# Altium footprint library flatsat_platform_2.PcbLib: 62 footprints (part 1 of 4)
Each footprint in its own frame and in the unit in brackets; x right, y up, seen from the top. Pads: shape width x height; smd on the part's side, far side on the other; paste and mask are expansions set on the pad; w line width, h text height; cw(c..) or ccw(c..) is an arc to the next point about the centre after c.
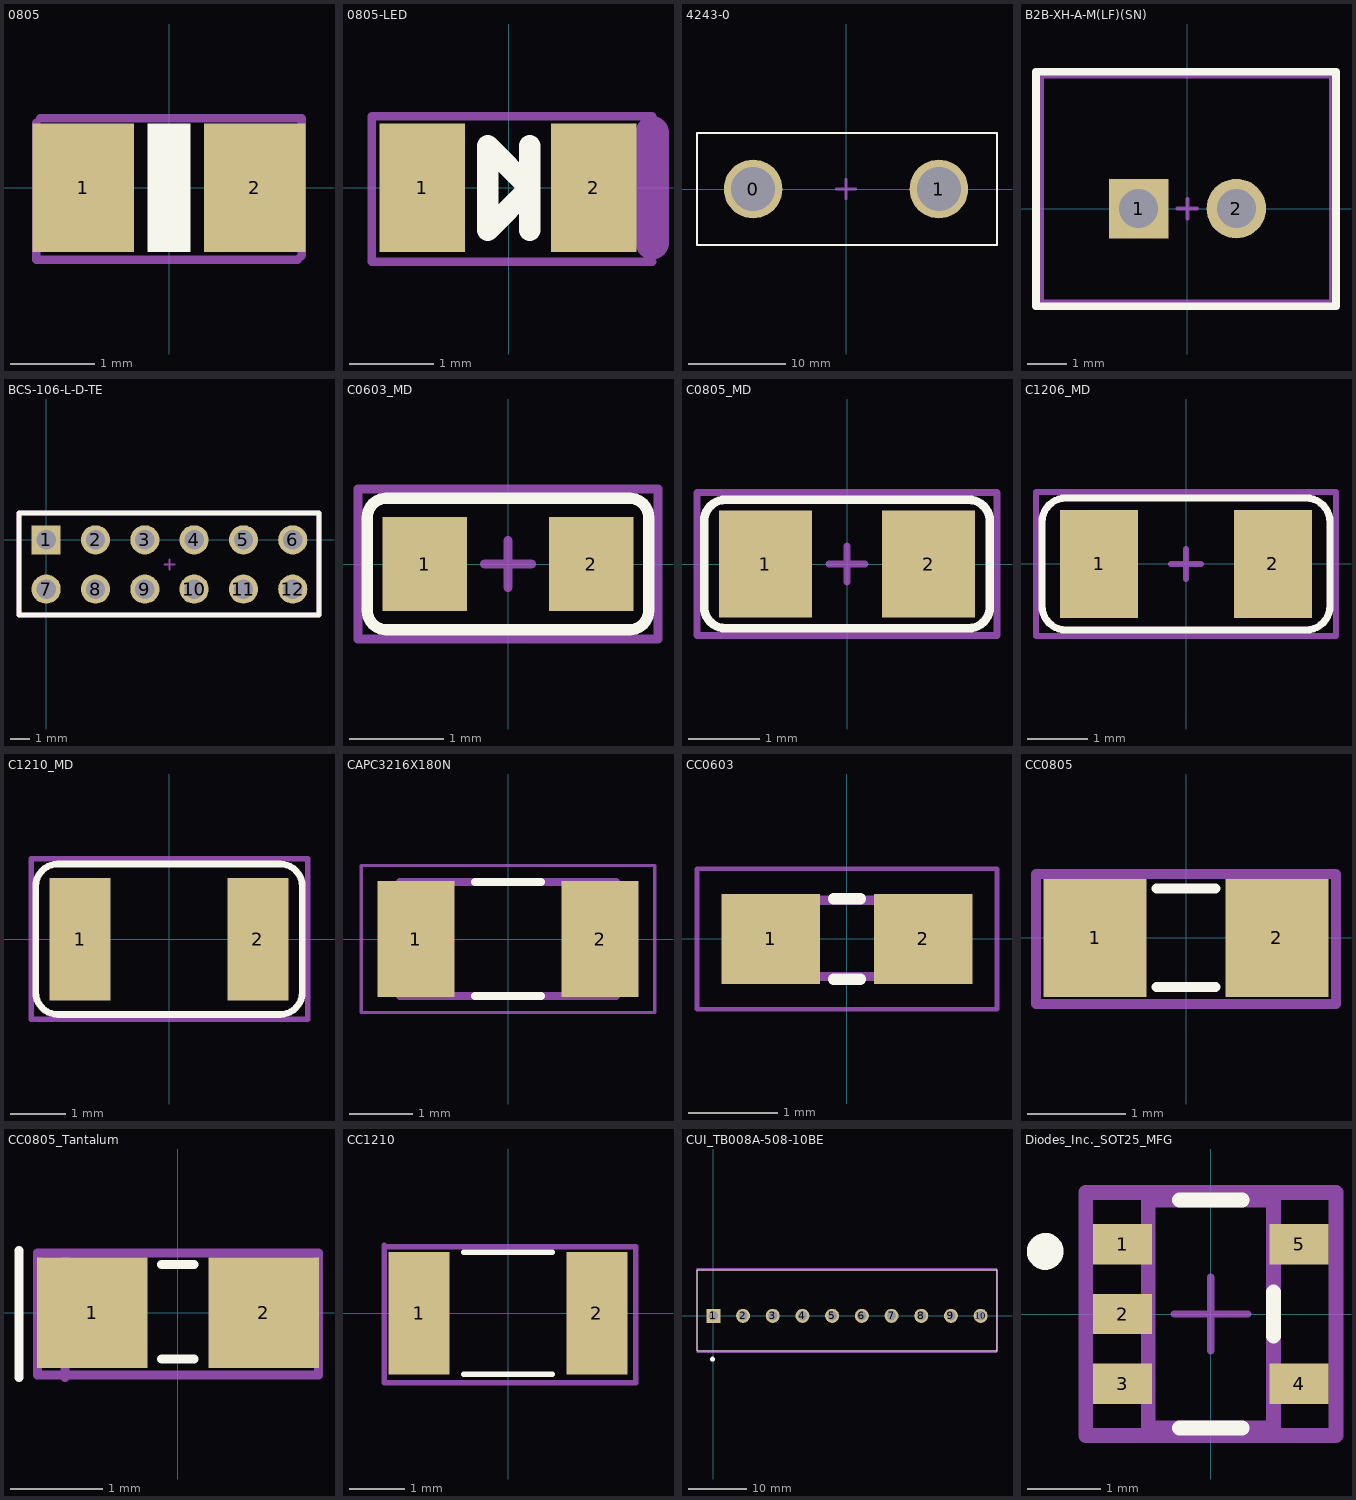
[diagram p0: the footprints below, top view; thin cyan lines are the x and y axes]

## 0805 [mil]
pads (2):
  rect 47.24x60 smd: 1(-40,0) 2(40,0)
Top Overlay:
  rectangle: -10,-30 10,30
Mechanical 15:
  lines w3.94: -62.01,30.51 -62.01,-33.46 60.04,-33.46 62.01,-31.5 62.01,32.48 -60.04,32.48
  text ".Designator" at -58.7,-2.44 h19.68
3D body "RES0805(2012M).STEP": height 31.1, standoff 0, extent -50,-24.49 48.75,24.51

## 0805-LED [mil]
height 122.05
pads (2):
  rect 40x60 smd: 1(-40.35,0) 2(39.65,0)
Top Overlay:
  lines w10: 9.84,-19.68 9.84,19.68 ; -9.84,-19.68 -9.84,19.68 9.84,0 -9.84,-19.68
Mechanical 15:
  lines w3.94: 66.93,-34.45 -63.98,-34.45 -63.98,33.46 66.93,33.46
  lines w15.75: 66.93,-25.59 66.93,25.59
  text ".Designator" at -41.34,-1.97 h19.68
3D body "User Library-led_0805LED0805_red.STEP": height 43.31, standoff 0, extent -39.76,-24.6 39.77,24.61

## 4243-0 [mm]
pads (2):
  round 6 hole 4.5: 0(-9.525,0) 1(9.525,0)
Top Overlay:
  lines w0.2: -15.275,-5.75 -15.275,5.75 15.475,5.75 15.475,-5.75 -15.275,-5.75
Top Assembly:
  lines w0.2: -15.275,-5.75 -15.275,5.75 15.475,5.75 15.475,-5.75 -15.275,-5.75
  lines w0.3: -1,0 1,0 ; 0,-1 0,1
  text "'.Designator'" at -6.525,2.5 h1.2
3D body: height 24.13, standoff 0, extent 3.925,-5.597 15.125,5.597
3D body: height 6, standoff 0, extent -15.125,-5.597 15.275,5.597
3D body: height 24.13, standoff 0, extent -15.125,-5.597 -3.925,5.597

## B2B-XH-A-M(LF)(SN) [mm]
pads (2):
  rect 1.524x1.524 hole 1: 1(-1.25,0)
  round 1.524 hole 1: 2(1.25,0)
Top Overlay:
  lines w0.2: -3.875,-2.5 3.8,-2.5 3.8,3.5 -3.875,3.5 -3.875,0.5 -3.875,-2.5
Top Assembly:
  lines w0.1: -0.25,0 0.25,0 ; 0,-0.25 0,0.25 ; -3.725,-2.375 3.675,-2.375 3.675,3.375 -3.725,3.375 -3.725,2.875 -3.725,-2.375
  text "'.Designator'" at -2.5,1.25 h1.2
3D body "B2B-XH-A(LF)(SN)--3DModel-STEP-56544.STEP": height 7.01, standoff -3.39, extent -3.753,-2.376 3.647,3.374

## BCS-106-L-D-TE [mm]
pads (12):
  rect 1.5x1.5 hole 1: 1(0,0)
  round 1.5 hole 1: 2(2.54,0) 3(5.08,0) 4(7.62,0) 5(10.16,0) 6(12.7,0) 7(0,-2.54) 8(2.54,-2.54) 9(5.08,-2.54) 10(7.62,-2.54) 11(10.16,-2.54) 12(12.7,-2.54)
Top Overlay:
  lines w0.254: -1.4,-3.87 -1.4,-1.27 -1.4,1.38 14.05,1.38 14.05,-3.87 -1.4,-3.87
Top Assembly:
  lines w0.1: 6.1,-1.27 6.6,-1.27 ; 6.35,-1.52 6.35,-1.02
  lines w0.254: -1.4,-3.87 -1.4,-1.27 -1.4,1.38 14.05,1.38 14.05,-3.87 -1.4,-3.87
  text "'.Designator'" at 0.25,-2.87 h0.8
3D body "BCS-106-L-D-TE.stp": height 7.38, standoff -3.09, extent -1.27,-3.81 13.97,1.27

## C0603_MD [mm] "Chip Capacitor, Body 1.6x0.8mm, IPC Medium Density"
height 0.85
pads (2):
  rect 0.9x1 smd: 1(-0.889,0) 2(0.889,0)
Top Overlay:
  lines w0.12: -1.5,-0.5 ccw(c-1.3,-0.5) -1.3,-0.7 1.3,-0.7 ccw(c1.3,-0.5) 1.5,-0.5 1.5,0.5 ccw(c1.3,0.5) 1.3,0.7 -1.3,0.7 ccw(c-1.3,0.5) -1.5,0.5 -1.5,-0.5
Top Assembly:
  lines w0.1: -0.25,0 0.25,0 ; 0,-0.25 0,0.25 ; -1.6,-0.8 -1.6,0.8 1.6,0.8 1.6,-0.8 -1.6,-0.8
  text "'.Designator'" at -1.5,-0.5 h0.8
3D body "C0603.step": height 0.79, standoff 0, extent -1,-0.406 1,0.381

## C0805_MD [mm] "Chip Capacitor, Body 2.0x1.3mm, IPC Medium Density"
height 1.1
pads (2):
  rect 1.3x1.5 smd: 1(-1.143,0) 2(1.143,0)
Top Overlay:
  lines w0.12: -2,-0.6 ccw(c-1.7,-0.6) -1.7,-0.9 1.7,-0.9 ccw(c1.7,-0.6) 2,-0.6 2,0.6 ccw(c1.7,0.6) 1.7,0.9 -1.7,0.9 ccw(c-1.7,0.6) -2,0.6 -2,-0.6
Top Assembly:
  lines w0.1: -0.25,0 0.25,0 ; 0,-0.25 0,0.25 ; -2.1,-1 -2.1,1 2.1,1 2.1,-1 -2.1,-1
  text "'.Designator'" at -1.8,-0.7 h0.8
3D body "C0805.step": height 0.79, standoff 0, extent -1.254,-0.61 1.254,0.635

## C1206_MD [mm] "Chip Capacitor, Body 3.2x1.6mm, IPC Medium Density"
height 1.35
pads (2):
  rect 1.3x1.8 smd: 1(-1.45,0) 2(1.45,0)
Top Overlay:
  lines w0.12: -2.4,-0.7 ccw(c-2,-0.7) -2,-1.1 2,-1.1 ccw(c2,-0.7) 2.4,-0.7 2.4,0.7 ccw(c2,0.7) 2,1.1 -2,1.1 ccw(c-2,0.7) -2.4,0.7 -2.4,-0.7
Top Assembly:
  lines w0.1: -0.25,0 0.25,0 ; 0,-0.25 0,0.25 ; -2.5,-1.2 2.5,-1.2 2.5,1.2 -2.5,1.2 -2.5,-1.2
  text "'.Designator'" at -2,-1 h0.8
3D body "C1206.step": height 1.53, standoff 0, extent -2,-0.813 2,0.788

## C1210_MD [mm] "TDK mlccspec_commercial_general_midvoltage_en.pdf"
height 2.5
pads (2):
  rect 1.1x2.2 smd: 1(-1.6,0) 2(1.6,0)
Top Overlay:
  lines w0.12: -2.4,0.947 -2.4,-0.954 ccw(c-2,-0.954) -2,-1.354 2,-1.354 ccw(c2,-0.954) 2.4,-0.954 2.4,0.953 ; -2.4,0.954 cw(c-2,0.954) -2,1.354 2,1.354 cw(c2,0.954) 2.4,0.954
Mechanical 15:
  lines w0.1: -2.48,-1.441 2.496,-1.441 2.496,1.45 -2.48,1.45 -2.48,-1.441
  text ".Designator" at -1.66,0.01 h0.5
3D body "CC1210(3225M).STEP": height 1.69, standoff -0.01, extent -2,-1.244 2,1.245

## CAPC3216X180N [mm]
pads (2):
  rect 1.21x1.82 smd: 1(-1.45,0) 2(1.45,0)
Top Overlay:
  lines w0.127: -0.52,-0.9 0.52,-0.9 ; -0.52,0.9 0.52,0.9
Mechanical 13:
  lines w0.127: -1.7,-0.9 1.7,-0.9 1.7,0.9 -1.7,0.9 -1.7,-0.9
Mechanical 15:
  lines w0.05: -2.308,-1.158 2.308,-1.158 2.308,1.158 -2.308,1.158 -2.308,-1.158
3D body "GRT31CR61H106KE01L.STEP": height 1.61, standoff 0.01, extent -1.6,-0.889 1.6,0.911

## CC0603 [mm]
pads (2):
  rect 1.1x1 smd: 1(-0.85,0) 2(0.85,0)
Top Overlay:
  lines w0.127: -0.15,-0.45 0.15,-0.45 ; -0.15,0.45 0.15,0.45
Mechanical 13:
  region: -0.338,-0.47 -0.839,-0.47 -0.839,0.48 -0.338,0.48
  region: 0.83,-0.471 0.331,-0.471 0.331,0.48 0.83,0.48
  lines w0.102: -0.356,-0.419 0.356,-0.419 ; -0.356,0.432 0.356,0.432
Mechanical 15:
  lines w0.051: -1.673,-0.783 1.673,-0.783 1.673,0.783 -1.673,0.783 -1.673,-0.783
3D body "C0603.step": height 0.79, standoff 0, extent -1,-0.406 1,0.381

## CC0805 [mm] "TDK mlccspec_commercial_general_midvoltage_en.pdf"
height 1.25
pads (2):
  rect 1.05x1.2 smd: 1(-0.925,0) 2(0.925,0)
Top Overlay:
  lines w0.1: -0.3,-0.5 0.3,-0.5 ; -0.3,0.5 0.3,0.5
Mechanical 15:
  lines w0.1: -1.525,-0.675 1.525,-0.675 1.525,0.65 -1.525,0.65 -1.525,-0.675
  text ".Designator" at -1.275,-0.075 h0.5
3D body "C0805.step": height 0.79, standoff 0, extent -1.254,-0.622 1.254,0.622

## CC0805_Tantalum [mm] "TDK mlccspec_commercial_general_midvoltage_en.pdf"
height 1.25
pads (2):
  rect 1.2x1.2 smd: 1(-0.93,0) 2(0.93,0)
Top Overlay:
  lines w0.1: -1.725,-0.7 -1.725,0.675 ; -0.175,-0.5 0.175,-0.5 ; -0.175,0.525 0.175,0.525
Mechanical 15:
  lines w0.1: -1.225,-0.7 -1.225,0.625 ; -1.525,-0.675 1.525,-0.675 1.525,0.65 -1.525,0.65 -1.525,-0.675
  text ".Designator" at 1.28,0.24 h0.5
3D body "User Library-Tantalum Capacitor Case R.STEP": height 1.35, standoff 0, extent -1.042,-0.585 1.208,0.765

## CC1210 [mm] "TDK mlccspec_commercial_general_midvoltage_en.pdf"
height 2.5
pads (2):
  rect 1.1x2.2 smd: 1(-1.6,0) 2(1.6,0)
Top Overlay:
  lines w0.1: -0.8,-1.1 0.8,-1.1 ; -0.8,1.1 0.8,1.1
Mechanical 15:
  lines w0.1: -2.225,1.225 -2.225,-1.25 2.3,-1.25 2.3,1.2 -2.175,1.2
  text ".Designator" at -1.66,0.01 h0.5
3D body "CC1210(3225M).STEP": height 1.69, standoff -0.01, extent -2,-1.244 2,1.245

## CUI_TB008A-508-10BE [mm]
pads (10):
  rect 2.4x2.4 hole 1.6: 1(0,0)
  round 2.4 hole 1.6: 2(5.08,0) 3(10.16,0) 4(15.24,0) 5(20.32,0) 6(25.4,0) 7(30.48,0) 8(35.56,0) 9(40.64,0) 10(45.72,0)
Top Overlay:
  circle w0.61: c-0.136,-7.412 r0.11
  lines w0.127: -2.794,-6 48.514,-6 48.514,7.874 -2.794,7.874 -2.794,-6
Mechanical 13:
  lines w0.127: -2.794,-6 48.514,-6 48.514,7.874 -2.794,7.874 -2.794,-6
Mechanical 15:
  lines w0.05: -2.79,-6.25 -2.79,8.14 48.51,8.14 48.51,-6.25 -2.79,-6.25
3D body "CUI_DEVICES_TB008A-508-10BE.step": height 15.83, standoff -3.49, extent -2.79,-6.015 48.51,7.874

## Diodes_Inc._SOT25_MFG [mm]
pads (5):
  rect 0.8x0.55 smd paste+0 mask+0: 1(-1.2,0.95) 2(-1.2,0) 3(-1.2,-0.95) 4(1.2,-0.95) 5(1.2,0.95)
Top Overlay:
  circle w0.25: c-2.25,0.85 r0.125
  lines w0.2: -0.425,-1.55 0.425,-1.55 ; -0.425,1.55 0.425,1.55 ; 0.85,-0.3 0.85,0.3
Mechanical 10:
  lines w0.2: -1.7,-1.65 -1.7,1.65 1.7,1.65 1.7,-1.65 -1.7,-1.65
  text ".Designator" at 0,0 h1
Mechanical 12:
  lines w0.2: -0.85,-1.55 -0.85,1.55 0.85,1.55 0.85,-1.55 -0.85,-1.55
Mechanical 15:
  lines w0.1: -0.5,0 0.5,0 ; 0,-0.5 0,0.5
  lines w0.2: -1.7,-1.65 -1.7,1.65 1.7,1.65 1.7,-1.65 -1.7,-1.65
3D body "IC_Diodes_Inc._AP331AWG-7_eec.STEP": height 0.25, standoff 0, extent -1.7,-1.65 1.7,1.65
